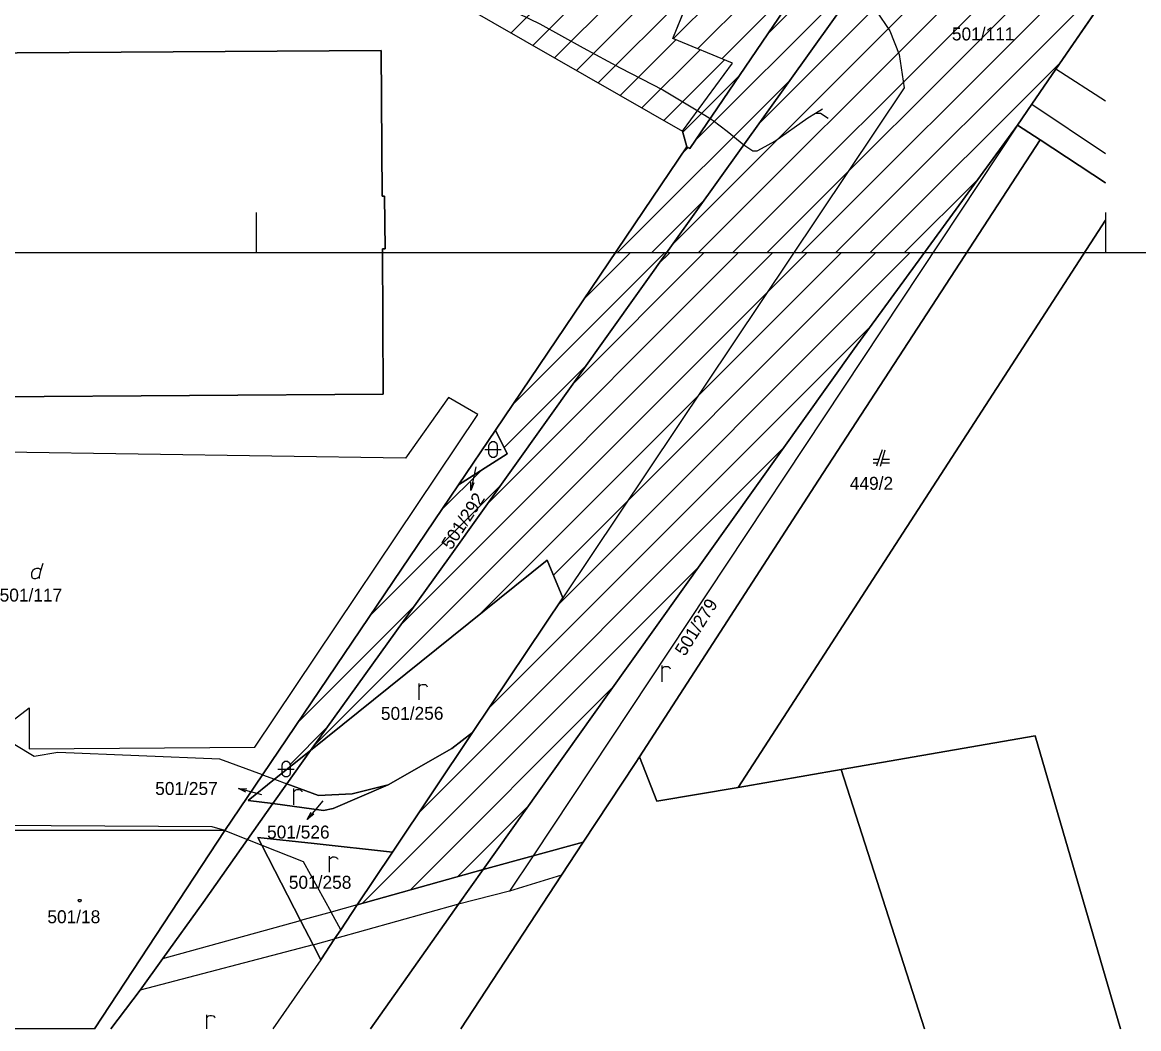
# Model space of a CAD drawing. Extents: x -264309 to -263505, y -1242443 to -1241763.
# Drawn here: x -263924.7 to -263786.7, y -1242443.4 to -1242319 of the extents above; entities that cross this region are included whole.
import ezdxf

# ---------------------------------------------------------------- set-up
doc = ezdxf.new("R2010")
doc.units = 0
for name, color, linetype in [('KN_2019_08_16', 7, 'Continuous'), ('KN_2019_08_16_KLADPAR', 7, 'Continuous'), ('KN_2019_08_16_ZAPPAR', 7, 'Continuous'), ('RAM_NA_TLAC_10xA4_1-500', 7, 'Continuous'), ('SRAFY_PARCELY', 7, 'Continuous')]:
    doc.layers.add(name, color=color, linetype=linetype)

msp = doc.modelspace()

# ---------------------------------------------------------------- linework, layer by layer
at = {"layer": 'KN_2019_08_16'}
for points in [[(-263867.42, -1242315.97), (-263860.78, -1242319.2), (-263855.41, -1242322.16), (-263850.82, -1242324.64), (-263845.54, -1242327.38), (-263841.25, -1242329.96), (-263839.72, -1242330.92), (-263839.35, -1242331.16), (-263837.6, -1242332.48), (-263835.55, -1242334.16), (-263834.45, -1242334.91), (-263833.91, -1242334.91), (-263833.34, -1242334.64), (-263831.7, -1242333.71), (-263827.64, -1242330.84), (-263826.7, -1242330.27), (-263825.81, -1242329.72)], [(-263826.7, -1242330.27), (-263826.06, -1242330.26), (-263825.1, -1242330.88)]]:
    msp.add_lwpolyline(points, dxfattribs=at)
at = {"layer": 'KN_2019_08_16_KLADPAR'}
for p, q in [((-263796.96, -1242324.83), (-263790.83, -1242315.89)), ((-263799.93, -1242329.15), (-263796.96, -1242324.83)), ((-263801.69, -1242331.72), (-263799.93, -1242329.15)), ((-263801.69, -1242331.72), (-263798.91, -1242333.55)), ((-263798.91, -1242333.55), (-263801.69, -1242331.72)), ((-263826.3, -1242375.62), (-263798.91, -1242333.55)), ((-263790.83, -1242338.85), (-263798.91, -1242333.55)), ((-263798.91, -1242333.55), (-263790.83, -1242338.85)), ((-263790.83, -1242343.48), (-263836.26, -1242413.64)), ((-263836.26, -1242413.64), (-263790.83, -1242343.48)), ((-263818.45, -1242371.88), (-263819.15, -1242373.88)), ((-263818.65, -1242373.88), (-263818.05, -1242371.88)), ((-263818.87, -1242373.08), (-263819.55, -1242373.08)), ((-263819.55, -1242373.48), (-263819.01, -1242373.48)), ((-263818.53, -1242373.48), (-263817.55, -1242373.48)), ((-263817.55, -1242373.08), (-263818.41, -1242373.08)), ((-263868.91, -1242375.98), (-263869.31, -1242376.91)), ((-263848.45, -1242409.83), (-263826.3, -1242375.62)), ((-263922.44, -1242386.81), (-263922.17, -1242385.91)), ((-263869.08, -1242406.85), (-263857.92, -1242390.17)), ((-263799.51, -1242407.26), (-263823.49, -1242411.42)), ((-263788.97, -1242443.45), (-263799.51, -1242407.26)), ((-263846.29, -1242415.3), (-263848.45, -1242409.83)), ((-263823.49, -1242411.42), (-263836.26, -1242413.64)), ((-263897.1, -1242414.2), (-263898.01, -1242413.74)), ((-263836.26, -1242413.64), (-263846.29, -1242415.3)), ((-263893.79, -1242415.62), (-263896.81, -1242415.22)), ((-263888.72, -1242416.94), (-263889.52, -1242417.57)), ((-263928.14, -1242418.9), (-263899.7, -1242418.94)), ((-263899.7, -1242418.94), (-263915.82, -1242443.45)), ((-263915.82, -1242443.45), (-263925.88, -1242443.45))]:
    msp.add_line(p, q, dxfattribs=at)
for points in [[(-263915.82, -1242443.45), (-263899.7, -1242418.94), (-263895.05, -1242412.05), (-263870.81, -1242376.19), (-263864.8, -1242372.36), (-263866.24, -1242369.43), (-263842.59, -1242334.42), (-263842.23, -1242334.63), (-263825.74, -1242310.33), (-263817.23, -1242297.78), (-263790.83, -1242258)], [(-263889.11, -1242409.04), (-263871.85, -1242385.03), (-263844.47, -1242346.65), (-263821.45, -1242314.43), (-263813.84, -1242303.78), (-263808.74, -1242296.68), (-263790.83, -1242271.71)], [(-263790.83, -1242271.71), (-263808.74, -1242296.68), (-263813.84, -1242303.78), (-263821.45, -1242314.43), (-263844.47, -1242346.65), (-263871.85, -1242385.03), (-263889.11, -1242409.04)], [(-263870.55, -1242316.79), (-263843.11, -1242332.49), (-263842.59, -1242334.42), (-263866.24, -1242369.43), (-263870.81, -1242376.19), (-263895.05, -1242412.05), (-263899.7, -1242418.94), (-263928.14, -1242418.9), (-263933.06, -1242418.97), (-263955.09, -1242419.03), (-263978.33, -1242419.1), (-263997.04, -1242419.26), (-264025.44, -1242419.01), (-264068.96, -1242418.63), (-264069.2, -1242359.38), (-264069.25, -1242345.54)], [(-263790.83, -1242315.89), (-263796.96, -1242324.83), (-263799.93, -1242329.15), (-263801.69, -1242331.72)], [(-263880.39, -1242322.51), (-263976.89, -1242323.14), (-263976.69, -1242353.26)], [(-263976.65, -1242359.72), (-263976.61, -1242365.64), (-263934.57, -1242365.37), (-263934.57, -1242365.72), (-263928.07, -1242365.67), (-263928.07, -1242365.32), (-263880.12, -1242365.01), (-263880.23, -1242347.02), (-263879.9, -1242347.02), (-263879.95, -1242340.53), (-263880.27, -1242340.53), (-263880.39, -1242322.51)], [(-263867.79, -1242423.76), (-263852.4, -1242402.18), (-263821.89, -1242359.4), (-263801.69, -1242331.72)], [(-263801.69, -1242331.72), (-263821.89, -1242359.4), (-263852.4, -1242402.18), (-263867.79, -1242423.76)], [(-263798.91, -1242333.55), (-263826.3, -1242375.62), (-263848.45, -1242409.83), (-263848.99, -1242410.65), (-263855.39, -1242420.39), (-263861.58, -1242422.07), (-263867.79, -1242423.76)], [(-263867.55, -1242371.84), (-263866.28, -1242371.84), (-263865.55, -1242371.84)], [(-263868.68, -1242373.98), (-263869.31, -1242376.91), (-263869.3, -1242375.89)], [(-263857.92, -1242390.17), (-263859.86, -1242385.54), (-263889.11, -1242409.04)], [(-263889.11, -1242409.04), (-263859.86, -1242385.54), (-263857.92, -1242390.17)], [(-263922.62, -1242387.8), (-263922.62, -1242387.53), (-263922.44, -1242386.81), (-263922.53, -1242386.63), (-263922.71, -1242386.54), (-263922.98, -1242386.54), (-263923.25, -1242386.63), (-263923.43, -1242386.81), (-263923.61, -1242387.08), (-263923.61, -1242387.44), (-263923.52, -1242387.71), (-263923.34, -1242387.8), (-263923.07, -1242387.8), (-263922.89, -1242387.71), (-263922.62, -1242387.53)], [(-263857.92, -1242390.17), (-263869.08, -1242406.85), (-263871.65, -1242408.8), (-263879.52, -1242413.3), (-263883.95, -1242414.4), (-263888.11, -1242414.6)], [(-263845.66, -1242400.55), (-263845.66, -1242399.28), (-263845.66, -1242398.55)], [(-263845.66, -1242398.95), (-263845.56, -1242398.82), (-263845.43, -1242398.71), (-263845.29, -1242398.66), (-263845.06, -1242398.65), (-263844.89, -1242398.68), (-263844.79, -1242398.75), (-263844.7, -1242398.85), (-263844.66, -1242398.95)], [(-263875.69, -1242402.78), (-263875.69, -1242401.51), (-263875.69, -1242400.78)], [(-263875.69, -1242401.18), (-263875.59, -1242401.05), (-263875.46, -1242400.94), (-263875.32, -1242400.89), (-263875.09, -1242400.88), (-263874.92, -1242400.91), (-263874.82, -1242400.98), (-263874.73, -1242401.08), (-263874.69, -1242401.18)], [(-263913.82, -1242443.45), (-263910.19, -1242438.67), (-263907.38, -1242434.76), (-263902.4, -1242427.83), (-263896.91, -1242420.05), (-263893.79, -1242415.62), (-263887.51, -1242416.47), (-263886.31, -1242416.23), (-263879.52, -1242413.3), (-263871.65, -1242408.8), (-263869.08, -1242406.85), (-263878.97, -1242421.64), (-263888.65, -1242420.54), (-263895.62, -1242419.81)], [(-263867.79, -1242423.76), (-263883.33, -1242428.15), (-263878.97, -1242421.64), (-263869.08, -1242406.85)], [(-263823.49, -1242411.42), (-263799.51, -1242407.26), (-263788.97, -1242443.45)], [(-263896.81, -1242415.22), (-263893.55, -1242412.6), (-263889.11, -1242409.04)], [(-263889.11, -1242409.04), (-263893.55, -1242412.6), (-263896.81, -1242415.22)], [(-263889.11, -1242409.04), (-263892.04, -1242413.16), (-263893.79, -1242415.62)], [(-263888.11, -1242414.6), (-263892.04, -1242413.16), (-263889.11, -1242409.04)], [(-263870.54, -1242443.45), (-263858.07, -1242424.48), (-263855.39, -1242420.39), (-263848.99, -1242410.65), (-263848.45, -1242409.83), (-263846.29, -1242415.3), (-263836.26, -1242413.64), (-263823.49, -1242411.42)], [(-263893.14, -1242411.36), (-263891.87, -1242411.36), (-263891.14, -1242411.36)], [(-263813.22, -1242443.45), (-263823.49, -1242411.42)], [(-263823.49, -1242411.42), (-263813.22, -1242443.45)], [(-263895.12, -1242414.54), (-263898.01, -1242413.74), (-263896.99, -1242413.81)], [(-263891.17, -1242415.77), (-263891.17, -1242414.5), (-263891.17, -1242413.77)], [(-263891.17, -1242414.17), (-263891.07, -1242414.04), (-263890.94, -1242413.93), (-263890.8, -1242413.88), (-263890.57, -1242413.87), (-263890.4, -1242413.9), (-263890.3, -1242413.97), (-263890.21, -1242414.07), (-263890.17, -1242414.17)], [(-263896.81, -1242415.22), (-263893.79, -1242415.62), (-263896.91, -1242420.05), (-263902.4, -1242427.83), (-263907.38, -1242434.76), (-263910.19, -1242438.67), (-263913.82, -1242443.45)], [(-263887.59, -1242415.28), (-263889.52, -1242417.57), (-263889.03, -1242416.68)], [(-263887.85, -1242434.92), (-263888.8, -1242433.08), (-263890.34, -1242430.07), (-263895.13, -1242420.76), (-263895.62, -1242419.81)], [(-263895.62, -1242419.81), (-263888.65, -1242420.54), (-263878.97, -1242421.64)], [(-263895.62, -1242419.81), (-263895.13, -1242420.76), (-263890.34, -1242430.07), (-263888.8, -1242433.08), (-263887.85, -1242434.92)], [(-263867.79, -1242423.76), (-263861.58, -1242422.07), (-263855.39, -1242420.39), (-263858.07, -1242424.48), (-263870.54, -1242443.45)], [(-263878.97, -1242421.64), (-263883.33, -1242428.15), (-263885.38, -1242431.22), (-263886.14, -1242432.36), (-263887.85, -1242434.92)], [(-263886.75, -1242424.11), (-263886.75, -1242422.84), (-263886.75, -1242422.11)], [(-263886.75, -1242422.51), (-263886.65, -1242422.38), (-263886.52, -1242422.27), (-263886.38, -1242422.22), (-263886.15, -1242422.21), (-263885.98, -1242422.24), (-263885.88, -1242422.31), (-263885.79, -1242422.41), (-263885.75, -1242422.51)], [(-263887.85, -1242434.92), (-263886.14, -1242432.36), (-263885.38, -1242431.22), (-263883.33, -1242428.15), (-263867.79, -1242423.76)], [(-263867.79, -1242423.76), (-263870.83, -1242428.07), (-263878.12, -1242438.39), (-263881.71, -1242443.45)], [(-263881.71, -1242443.45), (-263878.12, -1242438.39), (-263870.83, -1242428.07), (-263867.79, -1242423.76)], [(-263901.94, -1242443.45), (-263901.94, -1242442.45), (-263901.94, -1242441.72)], [(-263901.94, -1242442.12), (-263901.84, -1242441.99), (-263901.71, -1242441.88), (-263901.57, -1242441.83), (-263901.34, -1242441.82), (-263901.17, -1242441.85), (-263901.07, -1242441.92), (-263900.98, -1242442.02), (-263900.94, -1242442.12)]]:
    msp.add_lwpolyline(points, dxfattribs=at)
for points in [[(-263843.11, -1242332.49), (-263836.94, -1242324.08), (-263844.32, -1242321.02), (-263840.75, -1242312.15), (-263839.31, -1242310.28), (-263837.34, -1242308.65), (-263835.46, -1242307.53), (-263832.97, -1242307.02), (-263829.09, -1242308.37), (-263825.74, -1242310.33), (-263842.23, -1242334.63), (-263842.59, -1242334.42)], [(-263976.61, -1242365.64), (-263976.65, -1242359.72), (-263976.69, -1242353.26), (-263976.89, -1242323.14), (-263880.39, -1242322.51), (-263880.27, -1242340.53), (-263879.95, -1242340.53), (-263879.9, -1242347.02), (-263880.23, -1242347.02), (-263880.12, -1242365.01), (-263928.07, -1242365.32), (-263928.07, -1242365.67), (-263934.57, -1242365.72), (-263934.57, -1242365.37)], [(-263866.24, -1242369.43), (-263864.8, -1242372.36), (-263870.81, -1242376.19)], [(-263867.05, -1242371.34), (-263866.95, -1242371.05), (-263866.7, -1242370.87), (-263866.39, -1242370.87), (-263866.14, -1242371.05), (-263866.04, -1242371.34), (-263866.04, -1242372.34), (-263866.14, -1242372.63), (-263866.39, -1242372.81), (-263866.7, -1242372.81), (-263866.95, -1242372.63), (-263867.05, -1242372.34)], [(-263892.64, -1242410.86), (-263892.54, -1242410.57), (-263892.29, -1242410.39), (-263891.98, -1242410.39), (-263891.73, -1242410.57), (-263891.63, -1242410.86), (-263891.63, -1242411.86), (-263891.73, -1242412.15), (-263891.98, -1242412.33), (-263892.29, -1242412.33), (-263892.54, -1242412.15), (-263892.64, -1242411.86)], [(-263892.04, -1242413.16), (-263888.11, -1242414.6), (-263883.95, -1242414.4), (-263879.52, -1242413.3), (-263886.31, -1242416.23), (-263887.51, -1242416.47), (-263893.79, -1242415.62)], [(-263917.56, -1242427.46), (-263917.47, -1242427.61), (-263917.56, -1242427.76), (-263917.74, -1242427.76), (-263917.83, -1242427.61), (-263917.74, -1242427.46)]]:
    msp.add_lwpolyline(points, close=True, dxfattribs=at)
at = {"layer": 'KN_2019_08_16_ZAPPAR'}
for p, q in [((-263790.83, -1242328.78), (-263796.96, -1242324.83)), ((-263815.74, -1242327.13), (-263857.92, -1242390.17)), ((-263799.93, -1242329.15), (-263790.83, -1242335.24)), ((-263801.69, -1242331.72), (-263861.58, -1242422.07)), ((-263895.99, -1242408.63), (-263868.44, -1242367.53)), ((-263900.34, -1242410.11), (-263920.36, -1242409.31)), ((-263895.05, -1242412.05), (-263900.34, -1242410.11)), ((-263895.05, -1242412.05), (-263893.55, -1242412.6)), ((-263893.55, -1242412.6), (-263892.04, -1242413.16)), ((-263901.26, -1242418.49), (-264062.03, -1242417.63)), ((-263899.7, -1242418.94), (-263901.26, -1242418.49)), ((-263899.7, -1242418.94), (-263896.91, -1242420.05)), ((-263896.91, -1242420.05), (-263895.13, -1242420.76)), ((-263895.13, -1242420.76), (-263890.04, -1242422.78)), ((-263890.04, -1242422.78), (-263886.58, -1242429.04)), ((-263861.58, -1242422.07), (-263864.53, -1242426.44)), ((-263883.33, -1242428.15), (-263886.58, -1242429.04)), ((-263870.83, -1242428.07), (-263886.14, -1242432.36)), ((-263907.38, -1242434.76), (-263890.34, -1242430.07)), ((-263886.58, -1242429.04), (-263890.34, -1242430.07)), ((-263885.38, -1242431.22), (-263886.58, -1242429.04)), ((-263888.8, -1242433.08), (-263886.14, -1242432.36)), ((-263888.8, -1242433.08), (-263910.19, -1242438.67)), ((-263887.85, -1242434.92), (-263893.77, -1242443.45))]:
    msp.add_line(p, q, dxfattribs=at)
for points in [[(-263821.45, -1242314.43), (-263819.18, -1242317.59), (-263817.51, -1242320.07), (-263816.33, -1242322.99), (-263815.74, -1242327.13)], [(-263868.44, -1242367.53), (-263872.05, -1242365.41), (-263877.38, -1242372.91), (-263926.94, -1242372.17), (-263926.93, -1242369.21)], [(-263920.36, -1242409.31), (-263923.3, -1242409.8), (-263925.66, -1242408.34), (-263926.4, -1242405.7), (-263923.88, -1242403.8), (-263923.89, -1242408.83), (-263895.99, -1242408.63)], [(-263858.07, -1242424.48), (-263864.53, -1242426.44), (-263870.83, -1242428.07)]]:
    msp.add_lwpolyline(points, dxfattribs=at)
at = {"layer": 'RAM_NA_TLAC_10xA4_1-500'}
for p, q in [((-263895.83, -1242342.54), (-263895.83, -1242347.54)), ((-263790.83, -1242342.54), (-263790.83, -1242347.54))]:
    msp.add_line(p, q, dxfattribs=at)
msp.add_lwpolyline([(-264210.83, -1242050.54), (-264105.83, -1242050.54), (-264000.83, -1242050.54), (-263895.83, -1242050.54), (-263790.83, -1242050.54), (-263685.83, -1242050.54), (-263685.83, -1242199.04), (-263685.83, -1242347.54), (-263790.83, -1242347.54), (-263895.83, -1242347.54), (-264000.83, -1242347.54), (-264105.83, -1242347.54), (-264210.83, -1242347.54), (-264210.83, -1242199.04)], close=True, dxfattribs=at)
at = {"layer": 'SRAFY_PARCELY'}
for p, q in [((-263833.72, -1242331.6), (-263790.83, -1242288.71)), ((-263844.33, -1242346.46), (-263790.83, -1242292.95)), ((-263864.33, -1242320.35), (-263839.57, -1242295.58)), ((-263841.17, -1242347.54), (-263790.83, -1242297.19)), ((-263832.63, -1242320.49), (-263808.52, -1242296.38)), ((-263861.64, -1242321.89), (-263837.77, -1242298.03)), ((-263858.94, -1242323.43), (-263834.89, -1242299.39)), ((-263856.24, -1242324.98), (-263830.93, -1242299.67)), ((-263836.93, -1242347.54), (-263790.83, -1242301.44)), ((-263832.68, -1242347.54), (-263790.83, -1242305.68)), ((-263844.26, -1242321.05), (-263830.94, -1242307.73)), ((-263841.26, -1242322.29), (-263827.98, -1242309.02)), ((-263828.44, -1242347.54), (-263790.83, -1242309.92)), ((-263841.59, -1242333.69), (-263819.24, -1242311.34)), ((-263844.32, -1242321.02), (-263840.75, -1242312.15)), ((-263838.26, -1242323.53), (-263827.19, -1242312.46)), ((-263824.2, -1242347.54), (-263790.83, -1242314.16)), ((-263853.54, -1242326.52), (-263841.82, -1242314.8)), ((-263870.55, -1242316.79), (-263843.11, -1242332.49)), ((-263836.94, -1242324.08), (-263844.32, -1242321.02)), ((-263850.84, -1242328.07), (-263843.95, -1242321.17)), ((-263848.14, -1242329.61), (-263840.95, -1242322.42)), ((-263845.44, -1242331.15), (-263837.95, -1242323.66)), ((-263843.11, -1242332.49), (-263836.94, -1242324.08)), ((-263819.96, -1242347.54), (-263796.33, -1242323.91)), ((-263851.2, -1242347.54), (-263829.86, -1242326.2)), ((-263843.08, -1242332.6), (-263836.15, -1242325.66)), ((-263843.15, -1242335.25), (-263842.42, -1242334.52)), ((-263815.71, -1242347.54), (-263806.53, -1242338.36)), ((-263846.95, -1242347.54), (-263840.47, -1242341.06)), ((-263888.77, -1242408.56), (-263827.74, -1242347.54)), ((-263877.92, -1242393.47), (-263831.98, -1242347.54)), ((-263868.21, -1242392.25), (-263823.5, -1242347.54)), ((-263867.2, -1242378.51), (-263836.23, -1242347.54)), ((-263864.11, -1242366.27), (-263845.37, -1242347.54)), ((-263859.09, -1242387.37), (-263819.25, -1242347.54)), ((-263858.47, -1242391), (-263815.01, -1242347.54)), ((-263856.64, -1242363.71), (-263840.47, -1242347.54)), ((-263855.28, -1242353.2), (-263849.61, -1242347.54)), ((-263846.08, -1242348.9), (-263844.71, -1242347.54)), ((-263867.05, -1242403.82), (-263819.88, -1242356.65)), ((-263865.18, -1242371.59), (-263855, -1242361.4)), ((-263875.62, -1242416.63), (-263830.59, -1242371.6)), ((-263872.96, -1242379.36), (-263867.97, -1242374.38)), ((-263881.81, -1242392.46), (-263865.56, -1242376.21)), ((-263882.73, -1242427.98), (-263841.14, -1242386.39)), ((-263890.66, -1242405.55), (-263876.23, -1242391.13)), ((-263876.81, -1242426.31), (-263851.69, -1242401.19)), ((-263891.65, -1242410.79), (-263887.08, -1242406.22)), ((-263893.11, -1242412.25), (-263892.64, -1242411.78)), ((-263870.9, -1242424.64), (-263862.24, -1242415.98))]:
    msp.add_line(p, q, dxfattribs=at)

# ---------------------------------------------------------------- texts
at = {"layer": 'KN_2019_08_16_KLADPAR'}
for s, p in [('501/111', (-263809.82, -1242321.26)), ('449/2', (-263822.44, -1242376.82)), ('501/117', (-263927.55, -1242390.64)), ('501/526', (-263894.49, -1242419.94)), ('501/258', (-263891.8, -1242426.15)), ('501/18', (-263921.65, -1242430.41))]:
    msp.add_text(s, height=1.6, dxfattribs=at).set_placement(p)
for s, rotation, p in [('501/292', 56.8374, (-263871.71, -1242384.35)), ('501/279', 57.7541, (-263842.83, -1242397.49)), ('501/256', 0.2292, (-263880.41, -1242405.28)), ('501/257', 359.9894, (-263908.32, -1242414.55))]:
    msp.add_text(s, height=1.6, rotation=rotation, dxfattribs=at).set_placement(p)

doc.saveas('drawing.dxf')
